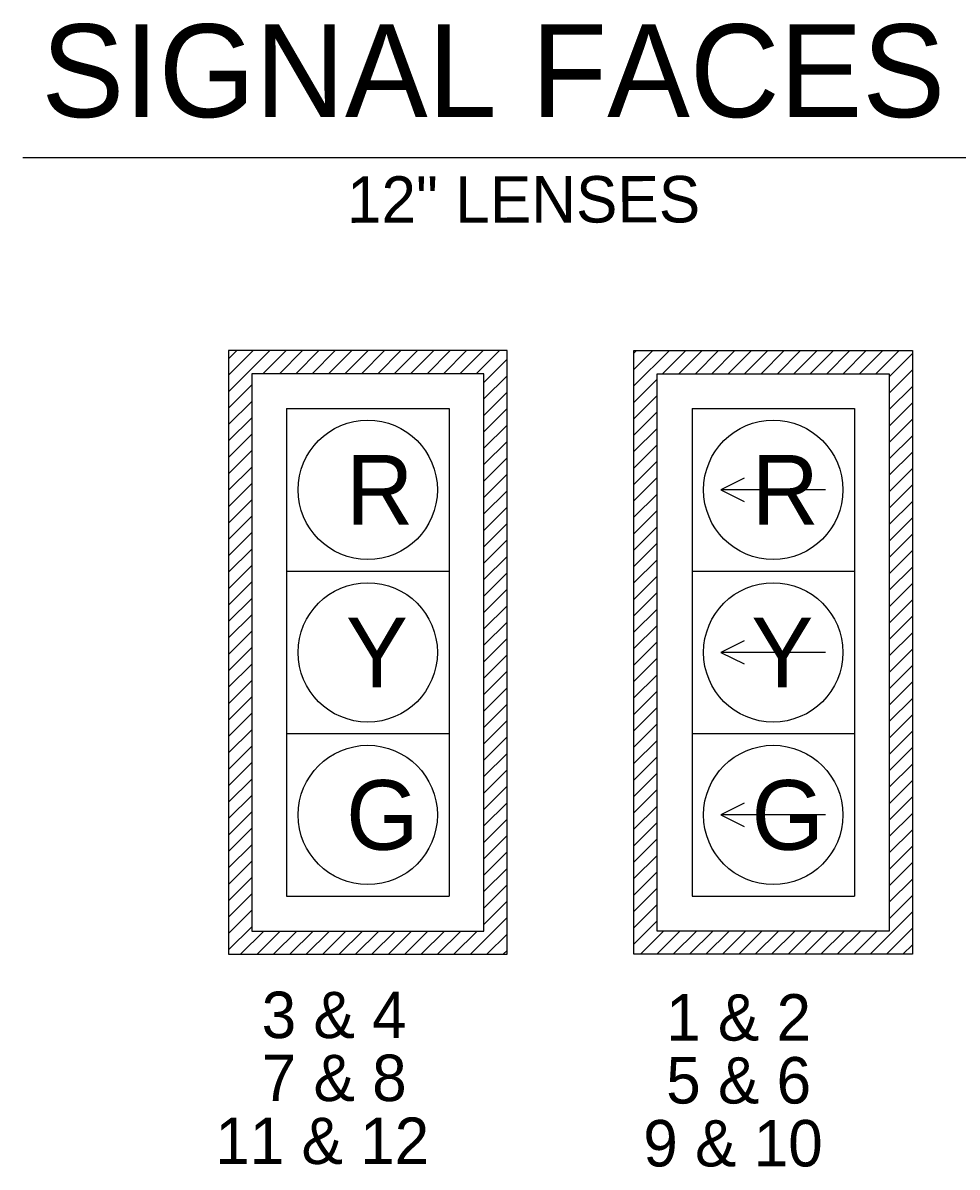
# Model space of a CAD drawing. Extents: x -19.5 to 29.5, y 0.4 to 10.6.
# Drawn here: x 3.589 to 4.931, y 8.759 to 10.401 of the extents above; entities that cross this region are included whole.
import ezdxf

# ---------------------------------------------------------------- set-up
doc = ezdxf.new("R2010")
doc.units = 0
doc.layers.add('T_Drafting', color=7, linetype='Continuous')
doc.layers.add('T_Notes', color=7, linetype='Continuous')

msp = doc.modelspace()

# ---------------------------------------------------------------- linework, layer by layer
at = {"layer": 'T_Drafting'}
for p, q in [((4.2841, 9.9307), (3.8841, 9.9307)), ((3.8841, 9.9307), (3.8841, 9.064)), ((3.8841, 9.8715), (3.9432, 9.9307)), ((3.8841, 9.8951), (3.9197, 9.9307)), ((3.8841, 9.9187), (3.8961, 9.9307)), ((3.9335, 9.8973), (3.9668, 9.9307)), ((3.9571, 9.8973), (3.9904, 9.9307)), ((3.9806, 9.8973), (4.014, 9.9307)), ((4.0042, 9.8973), (4.0375, 9.9307)), ((4.0278, 9.8973), (4.0611, 9.9307)), ((4.0513, 9.8973), (4.0847, 9.9307)), ((4.0749, 9.8973), (4.1082, 9.9307)), ((4.0985, 9.8973), (4.1318, 9.9307)), ((4.122, 9.8973), (4.1554, 9.9307)), ((4.1456, 9.8973), (4.1789, 9.9307)), ((4.1692, 9.8973), (4.2025, 9.9307)), ((4.1928, 9.8973), (4.2261, 9.9307)), ((4.2163, 9.8973), (4.2497, 9.9307)), ((4.2399, 9.8973), (4.2732, 9.9307)), ((4.2841, 9.064), (4.2841, 9.9307)), ((4.4664, 9.9307), (4.8664, 9.9307)), ((4.4664, 9.064), (4.4664, 9.9307)), ((4.4664, 9.8798), (4.5173, 9.9307)), ((4.4664, 9.9034), (4.4937, 9.9307)), ((4.4664, 9.927), (4.4701, 9.9307)), ((4.5075, 9.8973), (4.5408, 9.9307)), ((4.5311, 9.8973), (4.5644, 9.9307)), ((4.5546, 9.8973), (4.588, 9.9307)), ((4.5782, 9.8973), (4.6115, 9.9307)), ((4.6018, 9.8973), (4.6351, 9.9307)), ((4.6253, 9.8973), (4.6587, 9.9307)), ((4.6489, 9.8973), (4.6823, 9.9307)), ((4.6725, 9.8973), (4.7058, 9.9307)), ((4.6961, 9.8973), (4.7294, 9.9307)), ((4.7196, 9.8973), (4.753, 9.9307)), ((4.7432, 9.8973), (4.7765, 9.9307)), ((4.7668, 9.8973), (4.8001, 9.9307)), ((4.7903, 9.8973), (4.8237, 9.9307)), ((4.8139, 9.8973), (4.8472, 9.9307)), ((4.8331, 9.8929), (4.8664, 9.9263)), ((4.8664, 9.9307), (4.8664, 9.064)), ((4.2508, 9.8847), (4.2841, 9.918)), ((4.2508, 9.8611), (4.2841, 9.8944)), ((4.4664, 9.8562), (4.4998, 9.8896)), ((4.8331, 9.8694), (4.8664, 9.9027)), ((3.8841, 9.848), (3.9175, 9.8813)), ((4.2508, 9.8375), (4.2841, 9.8708)), ((4.8331, 9.8458), (4.8664, 9.8791)), ((3.8841, 9.8244), (3.9175, 9.8577)), ((4.4664, 9.8327), (4.4998, 9.866)), ((4.8331, 9.8222), (4.8664, 9.8556)), ((3.9675, 9.8473), (4.2008, 9.8473)), ((3.9675, 9.8473), (3.9675, 9.614)), ((4.2008, 9.8473), (4.2008, 9.614)), ((4.2508, 9.8139), (4.2841, 9.8473)), ((4.4664, 9.8091), (4.4998, 9.8424)), ((4.5498, 9.8473), (4.7831, 9.8473)), ((4.5498, 9.8473), (4.5498, 9.614)), ((4.7831, 9.8473), (4.7831, 9.614)), ((3.8841, 9.8008), (3.9175, 9.8342)), ((4.2508, 9.7904), (4.2841, 9.8237)), ((4.8331, 9.7987), (4.8664, 9.832)), ((3.8841, 9.7773), (3.9175, 9.8106)), ((4.4664, 9.7855), (4.4998, 9.8189)), ((4.8331, 9.7751), (4.8664, 9.8084)), ((4.2508, 9.7668), (4.2841, 9.8001)), ((4.4664, 9.762), (4.4998, 9.7953)), ((3.8841, 9.7537), (3.9175, 9.787)), ((4.2508, 9.7432), (4.2841, 9.7766)), ((4.8331, 9.7515), (4.8664, 9.7848)), ((3.8841, 9.7301), (3.9175, 9.7634)), ((4.4664, 9.7384), (4.4998, 9.7717)), ((4.8331, 9.7279), (4.8664, 9.7613)), ((3.8841, 9.7065), (3.9175, 9.7399)), ((4.2508, 9.7197), (4.2841, 9.753)), ((4.4664, 9.7148), (4.4998, 9.7482)), ((4.2508, 9.6961), (4.2841, 9.7294)), ((4.4664, 9.6913), (4.4998, 9.7246)), ((4.7414, 9.7307), (4.5914, 9.7307)), ((4.8331, 9.7044), (4.8664, 9.7377)), ((3.8841, 9.683), (3.9175, 9.7163)), ((4.8331, 9.6808), (4.8664, 9.7141)), ((3.8841, 9.6594), (3.9175, 9.6927)), ((4.2508, 9.6725), (4.2841, 9.7059)), ((4.4664, 9.6677), (4.4998, 9.701)), ((4.8331, 9.6572), (4.8664, 9.6906)), ((4.2508, 9.6489), (4.2841, 9.6823)), ((4.4664, 9.6441), (4.4998, 9.6775)), ((3.8841, 9.6358), (3.9175, 9.6692)), ((4.2508, 9.6254), (4.2841, 9.6587)), ((4.8331, 9.6337), (4.8664, 9.667)), ((3.8841, 9.6123), (3.9175, 9.6456)), ((4.4664, 9.6205), (4.4998, 9.6539)), ((4.8331, 9.6101), (4.8664, 9.6434)), ((4.2508, 9.6018), (4.2841, 9.6351)), ((4.4664, 9.597), (4.4998, 9.6303)), ((3.8841, 9.5887), (3.9175, 9.622)), ((3.9675, 9.614), (4.2008, 9.614)), ((3.9675, 9.614), (3.9675, 9.3807)), ((4.2008, 9.614), (4.2008, 9.3807)), ((4.2508, 9.5782), (4.2841, 9.6116)), ((4.5498, 9.614), (4.7831, 9.614)), ((4.5498, 9.614), (4.5498, 9.3807)), ((4.7831, 9.614), (4.7831, 9.3807)), ((4.8331, 9.5865), (4.8664, 9.6199)), ((3.8841, 9.5651), (3.9175, 9.5985)), ((4.4664, 9.5734), (4.4998, 9.6067)), ((4.8331, 9.5629), (4.8664, 9.5963)), ((4.2508, 9.5547), (4.2841, 9.588)), ((4.4664, 9.5498), (4.4998, 9.5832)), ((3.8841, 9.5416), (3.9175, 9.5749)), ((4.2508, 9.5311), (4.2841, 9.5644)), ((4.4664, 9.5263), (4.4998, 9.5596)), ((4.8331, 9.5394), (4.8664, 9.5727)), ((3.8841, 9.518), (3.9175, 9.5513)), ((4.8331, 9.5158), (4.8664, 9.5491)), ((3.8841, 9.4944), (3.9175, 9.5277)), ((4.2508, 9.5075), (4.2841, 9.5409)), ((4.4664, 9.5027), (4.4998, 9.536)), ((4.2508, 9.484), (4.2841, 9.5173)), ((4.4664, 9.4791), (4.4998, 9.5125)), ((4.8331, 9.4922), (4.8664, 9.5256)), ((3.8841, 9.4708), (3.9175, 9.5042)), ((4.2508, 9.4604), (4.2841, 9.4937)), ((4.7414, 9.4973), (4.5914, 9.4973)), ((4.8331, 9.4687), (4.8664, 9.502)), ((3.8841, 9.4473), (3.9175, 9.4806)), ((4.4664, 9.4556), (4.4998, 9.4889)), ((4.8331, 9.4451), (4.8664, 9.4784)), ((4.2508, 9.4368), (4.2841, 9.4702)), ((4.4664, 9.432), (4.4998, 9.4653)), ((3.8841, 9.4237), (3.9175, 9.457)), ((4.2508, 9.4132), (4.2841, 9.4466)), ((4.8331, 9.4215), (4.8664, 9.4549)), ((3.8841, 9.4001), (3.9175, 9.4335)), ((4.4664, 9.4084), (4.4998, 9.4417)), ((4.8331, 9.398), (4.8664, 9.4313)), ((4.2508, 9.3897), (4.2841, 9.423)), ((4.4664, 9.3848), (4.4998, 9.4182)), ((3.8841, 9.3766), (3.9175, 9.4099)), ((4.2508, 9.3661), (4.2841, 9.3994)), ((4.4664, 9.3613), (4.4998, 9.3946)), ((4.8331, 9.3744), (4.8664, 9.4077)), ((3.8841, 9.353), (3.9175, 9.3863)), ((3.9675, 9.3807), (4.2008, 9.3807)), ((3.9675, 9.3807), (3.9675, 9.1473)), ((4.2008, 9.3807), (4.2008, 9.1473)), ((4.5498, 9.3807), (4.7831, 9.3807)), ((4.5498, 9.3807), (4.5498, 9.1473)), ((4.7831, 9.3807), (4.7831, 9.1473)), ((4.8331, 9.3508), (4.8664, 9.3842)), ((3.8841, 9.3294), (3.9175, 9.3628)), ((4.2508, 9.3425), (4.2841, 9.3759)), ((4.4664, 9.3377), (4.4998, 9.371)), ((4.2508, 9.319), (4.2841, 9.3523)), ((4.4664, 9.3141), (4.4998, 9.3475)), ((4.8331, 9.3272), (4.8664, 9.3606)), ((3.8841, 9.3059), (3.9175, 9.3392)), ((4.8331, 9.3037), (4.8664, 9.337)), ((3.8841, 9.2823), (3.9175, 9.3156)), ((4.2508, 9.2954), (4.2841, 9.3287)), ((4.4664, 9.2906), (4.4998, 9.3239)), ((4.8331, 9.2801), (4.8664, 9.3134)), ((4.2508, 9.2718), (4.2841, 9.3052)), ((4.4664, 9.267), (4.4998, 9.3003)), ((3.8841, 9.2587), (3.9175, 9.292)), ((4.2508, 9.2483), (4.2841, 9.2816)), ((4.8331, 9.2565), (4.8664, 9.2899)), ((3.8841, 9.2351), (3.9175, 9.2685)), ((4.4664, 9.2434), (4.4998, 9.2768)), ((4.7414, 9.264), (4.5914, 9.264)), ((4.8331, 9.233), (4.8664, 9.2663)), ((4.2508, 9.2247), (4.2841, 9.258)), ((4.4664, 9.2199), (4.4998, 9.2532)), ((3.8841, 9.2116), (3.9175, 9.2449)), ((4.2508, 9.2011), (4.2841, 9.2344)), ((4.8331, 9.2094), (4.8664, 9.2427)), ((3.8841, 9.188), (3.9175, 9.2213)), ((4.4664, 9.1963), (4.4998, 9.2296)), ((4.8331, 9.1858), (4.8664, 9.2192)), ((3.8841, 9.1644), (3.9175, 9.1978)), ((4.2508, 9.1775), (4.2841, 9.2109)), ((4.4664, 9.1727), (4.4998, 9.206)), ((4.2508, 9.154), (4.2841, 9.1873)), ((4.4664, 9.1491), (4.4998, 9.1825)), ((4.8331, 9.1623), (4.8664, 9.1956)), ((3.8841, 9.1409), (3.9175, 9.1742)), ((4.8331, 9.1387), (4.8664, 9.172)), ((3.8841, 9.1173), (3.9175, 9.1506)), ((4.2508, 9.1304), (4.2841, 9.1637)), ((4.4664, 9.1256), (4.4998, 9.1589)), ((4.8331, 9.1151), (4.8664, 9.1484)), ((3.9675, 9.1473), (4.2008, 9.1473)), ((4.2508, 9.1068), (4.2841, 9.1402)), ((4.4664, 9.102), (4.4998, 9.1353)), ((4.5498, 9.1473), (4.7831, 9.1473)), ((3.8841, 9.0937), (3.9175, 9.1271)), ((4.2315, 9.064), (4.2841, 9.1166)), ((4.8055, 9.064), (4.8664, 9.1249)), ((3.8841, 9.0702), (3.9175, 9.1035)), ((4.4664, 9.0784), (4.4998, 9.1118)), ((4.8291, 9.064), (4.8664, 9.1013)), ((3.9015, 9.064), (3.9349, 9.0973)), ((3.9251, 9.064), (3.9584, 9.0973)), ((3.9487, 9.064), (3.982, 9.0973)), ((3.9722, 9.064), (4.0056, 9.0973)), ((3.9958, 9.064), (4.0292, 9.0973)), ((4.0194, 9.064), (4.0527, 9.0973)), ((4.043, 9.064), (4.0763, 9.0973)), ((4.0665, 9.064), (4.0999, 9.0973)), ((4.0901, 9.064), (4.1234, 9.0973)), ((4.1137, 9.064), (4.147, 9.0973)), ((4.1372, 9.064), (4.1706, 9.0973)), ((4.1608, 9.064), (4.1941, 9.0973)), ((4.1844, 9.064), (4.2177, 9.0973)), ((4.2079, 9.064), (4.2413, 9.0973)), ((4.2551, 9.064), (4.2841, 9.093)), ((4.4756, 9.064), (4.5089, 9.0973)), ((4.4991, 9.064), (4.5325, 9.0973)), ((4.5227, 9.064), (4.556, 9.0973)), ((4.5463, 9.064), (4.5796, 9.0973)), ((4.5698, 9.064), (4.6032, 9.0973)), ((4.5934, 9.064), (4.6267, 9.0973)), ((4.617, 9.064), (4.6503, 9.0973)), ((4.6405, 9.064), (4.6739, 9.0973)), ((4.6641, 9.064), (4.6974, 9.0973)), ((4.6877, 9.064), (4.721, 9.0973)), ((4.7113, 9.064), (4.7446, 9.0973)), ((4.7348, 9.064), (4.7682, 9.0973)), ((4.7584, 9.064), (4.7917, 9.0973)), ((4.782, 9.064), (4.8153, 9.0973)), ((4.2787, 9.064), (4.2841, 9.0695)), ((4.8527, 9.064), (4.8664, 9.0777)), ((3.8841, 9.064), (4.2841, 9.064)), ((4.8664, 9.064), (4.4664, 9.064))]:
    msp.add_line(p, q, dxfattribs=at)
for points in [[(4.2508, 9.0973), (4.2508, 9.8973), (3.9175, 9.8973), (3.9175, 9.0973)], [(4.4998, 9.8973), (4.8331, 9.8973), (4.8331, 9.0973), (4.4998, 9.0973)]]:
    msp.add_lwpolyline(points, close=True, dxfattribs=at)
for points in [[(4.6248, 9.7473), (4.5914, 9.7307), (4.6248, 9.714)], [(4.6248, 9.514), (4.5914, 9.4973), (4.6248, 9.4807)], [(4.6248, 9.2807), (4.5914, 9.264), (4.6248, 9.2473)]]:
    msp.add_lwpolyline(points, dxfattribs=at)
for centre in [(4.0841, 9.7307), (4.6664, 9.7307), (4.0841, 9.4973), (4.6664, 9.4973), (4.0841, 9.264), (4.6664, 9.264)]:
    msp.add_circle(centre, 0.1, dxfattribs=at)
at = {"layer": 'T_Notes'}
msp.add_line((3.5887, 10.2078), (5.2251, 10.2078), dxfattribs=at)

# ---------------------------------------------------------------- texts
at = {"layer": 'T_Drafting'}
msp.add_text('12" LENSES', height=0.06667, rotation=0.072, dxfattribs=at).set_placement((4.0542, 10.1139))
for s, p in [('R', (4.053, 9.6807)), ('R', (4.6353, 9.6807)), ('Y', (4.0526, 9.4473)), ('Y', (4.6349, 9.4473)), ('G', (4.053, 9.214)), ('G', (4.6353, 9.214))]:
    msp.add_text(s, height=0.1, dxfattribs=at).set_placement(p)
at = {"layer": 'T_Notes'}
for s, height, p in [('SIGNAL FACES', 0.133333, (3.6154, 10.2656)), ('3 & 4', 0.06667, (3.9317, 8.9437)), ('1 & 2', 0.06667, (4.5126, 8.9401)), ('7 & 8', 0.06667, (3.9318, 8.8533)), ('5 & 6', 0.06667, (4.5127, 8.8498)), ('11 & 12', 0.06667, (3.865, 8.763)), ('9 & 10', 0.06667, (4.4798, 8.7595))]:
    msp.add_text(s, height=height, dxfattribs=at).set_placement(p)

doc.saveas('drawing.dxf')
